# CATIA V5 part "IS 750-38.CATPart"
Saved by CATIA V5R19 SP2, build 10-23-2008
Part number: IS 750-38
Bounding box of the stored display mesh (mm): x -24.865 to 24.865, y -24.997 to 24.997, z 0 to 171
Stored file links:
  C:\Users\Bora\Desktop\3D Katı model\IS serisi\IS 750\IS 750-38.CATPart
  C:\Program Files\Dassault Systemes\B19\intel_a\reffiles\standard\MetricThickPitch.txt
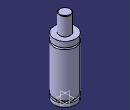
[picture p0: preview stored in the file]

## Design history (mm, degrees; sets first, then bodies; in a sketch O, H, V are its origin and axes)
Body1 (main body)
  Sketch1 on yz-plane, origin (0, 0, 0), H (0, 1, 0), V (0, 0, 1)
    point P3 (12.5, 170)
    point P5 (12.5, 170)
    point P10 (25, 113.5)
    point P11 (25, 117.5)
    point P13 (25, 117.5)
    point P14 (25, 113.5)
    line L1 (25, 0) -> (25, 8)
    line L2 (12.5, 170) -> (12.5, 130)
    arc A1 centre (11.5, 170) radius 1 from (12.5, 170) to (11.5, 171) ccw
    line L3 (21.5, 13) -> (21.5, 8)
    line L4 (25, 13) -> (25, 113.5)
    line L5 (25, 117.5) -> (25, 130)
    arc A2 centre (25, 115.5) radius 2 from (25, 117.5) to (25, 113.5) ccw
    line L6 (11.5, 171) -> (0, 171)
    point P15 (0, 171)
    line L7 (12.5, 130) -> (25, 130)
    line L8 (0, 0) -> (25, 0)
    line L9 (21.5, 8) -> (25, 8)
    line L10 (21.5, 13) -> (25, 13)
    coincidence: P15 V, P3 P5, P10 P14, P11 P13
    tangency: L6 A1
    horizontal: L7 H, L8 H, L9 H, L10 H
  Shaft1: profile Sketch1, axis Sketch1.V, angle 360
  Sketch2 on face of Shaft1 from Sketch1.L8, origin (0, 0, 0), H (1, 0, 0), V (0, -1, 0)
    point P1 (-10, 0)
    distance P1 V = 10
  Hole1: placed by Sketch2, at (-10, 0, 0) direction (0, 0, 1), diameter 6.647, depth 13, threaded "M8", thread diameter 8, thread depth 13, pitch 1.25
  Sketch3 on face of Shaft1 from Sketch1.L8, origin (0, 0, 0), H (1, 0, 0), V (0, -1, 0)
    point P1 (10, 0)
    distance V P1 = 10
  Hole2: placed by Sketch3, at (10, 0, 0) direction (0, 0, 1), diameter 6.647, depth 13, threaded "M8", thread diameter 8, thread depth 13, pitch 1.25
